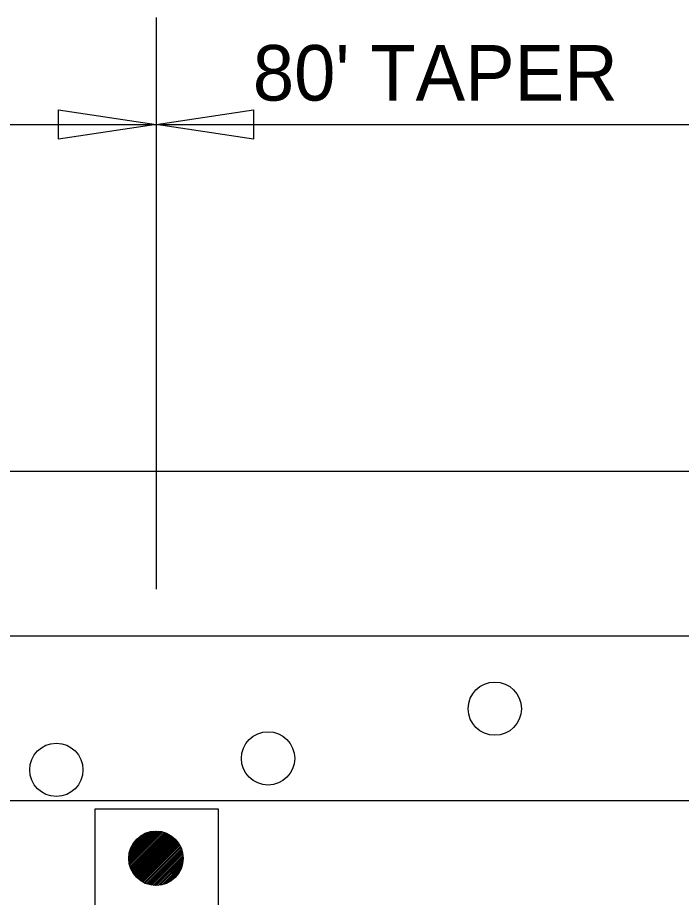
# Model space of a CAD drawing. Extents: x 1930579 to 1934718, y 596452 to 597844.
# Drawn here: x 1933104.2 to 1933176, y 597385.4 to 597480.5 of the extents above; entities that cross this region are included whole.
import ezdxf

# ---------------------------------------------------------------- set-up
doc = ezdxf.new("R2010")
doc.units = 0
doc.layers.add('Default', color=7, linetype='Continuous')

msp = doc.modelspace()

# ---------------------------------------------------------------- linework, layer by layer
at = {"layer": 'Default'}
for p, q in [((1933119.195, 597480.481), (1933119.195, 597418.728)), ((1933108.652, 597467.357), (1933108.652, 597470.522)), ((1933108.652, 597470.522), (1933119.195, 597468.94)), ((1933119.195, 597468.94), (1933129.738, 597470.522)), ((1933129.738, 597470.522), (1933129.738, 597467.357)), ((1933068.524, 597468.94), (1933119.195, 597468.94)), ((1933119.195, 597468.94), (1933108.652, 597467.357)), ((1933119.195, 597468.94), (1933193.131, 597468.94)), ((1933129.738, 597467.357), (1933119.195, 597468.94)), ((1932535.516, 597431.504), (1933637.519, 597431.504)), ((1932443.385, 597413.715), (1933637.519, 597413.715)), ((1932535.516, 597395.925), (1933637.519, 597395.925)), ((1933116.235, 597389.718), (1933119.134, 597392.617)), ((1933116.238, 597389.54), (1933119.312, 597392.614)), ((1933116.244, 597389.908), (1933118.945, 597392.608)), ((1933116.251, 597389.372), (1933119.481, 597392.601)), ((1933116.268, 597390.112), (1933118.74, 597392.585)), ((1933116.272, 597389.212), (1933119.641, 597392.58)), ((1933116.3, 597389.059), (1933119.793, 597392.552)), ((1933116.31, 597390.335), (1933118.517, 597392.542)), ((1933116.336, 597388.914), (1933119.939, 597392.517)), ((1933116.377, 597388.774), (1933120.078, 597392.476)), ((1933116.379, 597390.585), (1933118.267, 597392.473)), ((1933116.424, 597388.64), (1933120.213, 597392.429)), ((1933116.476, 597388.511), (1933120.341, 597392.377)), ((1933116.493, 597390.88), (1933117.972, 597392.359)), ((1933116.532, 597388.387), (1933120.465, 597392.32)), ((1933116.594, 597388.268), (1933120.585, 597392.258)), ((1933116.66, 597388.153), (1933120.7, 597392.192)), ((1933116.71, 597391.277), (1933117.575, 597392.143)), ((1933116.73, 597388.042), (1933120.81, 597392.122)), ((1933116.805, 597387.936), (1933120.917, 597392.048)), ((1933116.883, 597387.833), (1933121.019, 597391.969)), ((1933116.966, 597387.735), (1933121.117, 597391.886)), ((1933117.052, 597387.641), (1933121.212, 597391.8)), ((1933117.143, 597387.55), (1933121.302, 597391.709)), ((1933117.237, 597387.464), (1933121.389, 597391.615)), ((1933117.336, 597387.381), (1933121.471, 597391.517)), ((1933117.438, 597387.303), (1933121.55, 597391.414)), ((1933117.544, 597387.228), (1933121.624, 597391.308)), ((1933117.655, 597387.158), (1933121.694, 597391.197)), ((1933117.77, 597387.092), (1933121.76, 597391.082)), ((1933117.889, 597387.03), (1933121.822, 597390.963)), ((1933118.013, 597386.974), (1933121.879, 597390.839)), ((1933118.142, 597386.922), (1933121.931, 597390.71)), ((1933118.276, 597386.875), (1933121.977, 597390.576)), ((1933118.416, 597386.834), (1933122.019, 597390.436)), ((1933118.562, 597386.799), (1933122.054, 597390.29)), ((1933118.715, 597386.77), (1933122.082, 597390.138)), ((1933118.874, 597386.749), (1933122.103, 597389.978)), ((1933119.043, 597386.737), (1933122.116, 597389.81)), ((1933119.221, 597386.734), (1933122.118, 597389.631)), ((1933119.411, 597386.743), (1933122.109, 597389.441)), ((1933119.615, 597386.767), (1933122.086, 597389.237)), ((1933119.839, 597386.809), (1933122.043, 597389.014)), ((1933120.089, 597386.879), (1933121.974, 597388.763)), ((1933120.384, 597386.993), (1933121.859, 597388.468)), ((1933120.783, 597387.211), (1933121.641, 597388.069))]:
    msp.add_line(p, q, dxfattribs=at)
msp.add_lwpolyline([(1933112.601, 597395.028), (1933125.894, 597395.028), (1933125.894, 597370.493), (1933112.601, 597370.493)], close=True, dxfattribs=at)
for centre, radius in [((1933155.791, 597405.833), 2.878), ((1933131.294, 597400.466), 2.878), ((1933108.416, 597399.228), 2.878), ((1933119.177, 597389.675), 2.942)]:
    msp.add_circle(centre, radius, dxfattribs=at)

# ---------------------------------------------------------------- texts
msp.add_text("80' TAPER", height=5.9996, rotation=360, dxfattribs=at).set_placement((1933129.647, 597471.514))

doc.saveas('drawing.dxf')
